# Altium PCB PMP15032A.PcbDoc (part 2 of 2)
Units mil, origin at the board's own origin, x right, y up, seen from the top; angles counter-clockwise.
Board outline 3900 x 2580 mil, 6 copper layers (Top Layer, Signal Layer 1, Signal Layer 2, Signal Layer 3, Signal Layer 4, Bottom Layer), stack 61.668 mil thick; 127 components, 51 nets, 282 pads, 427 vias.
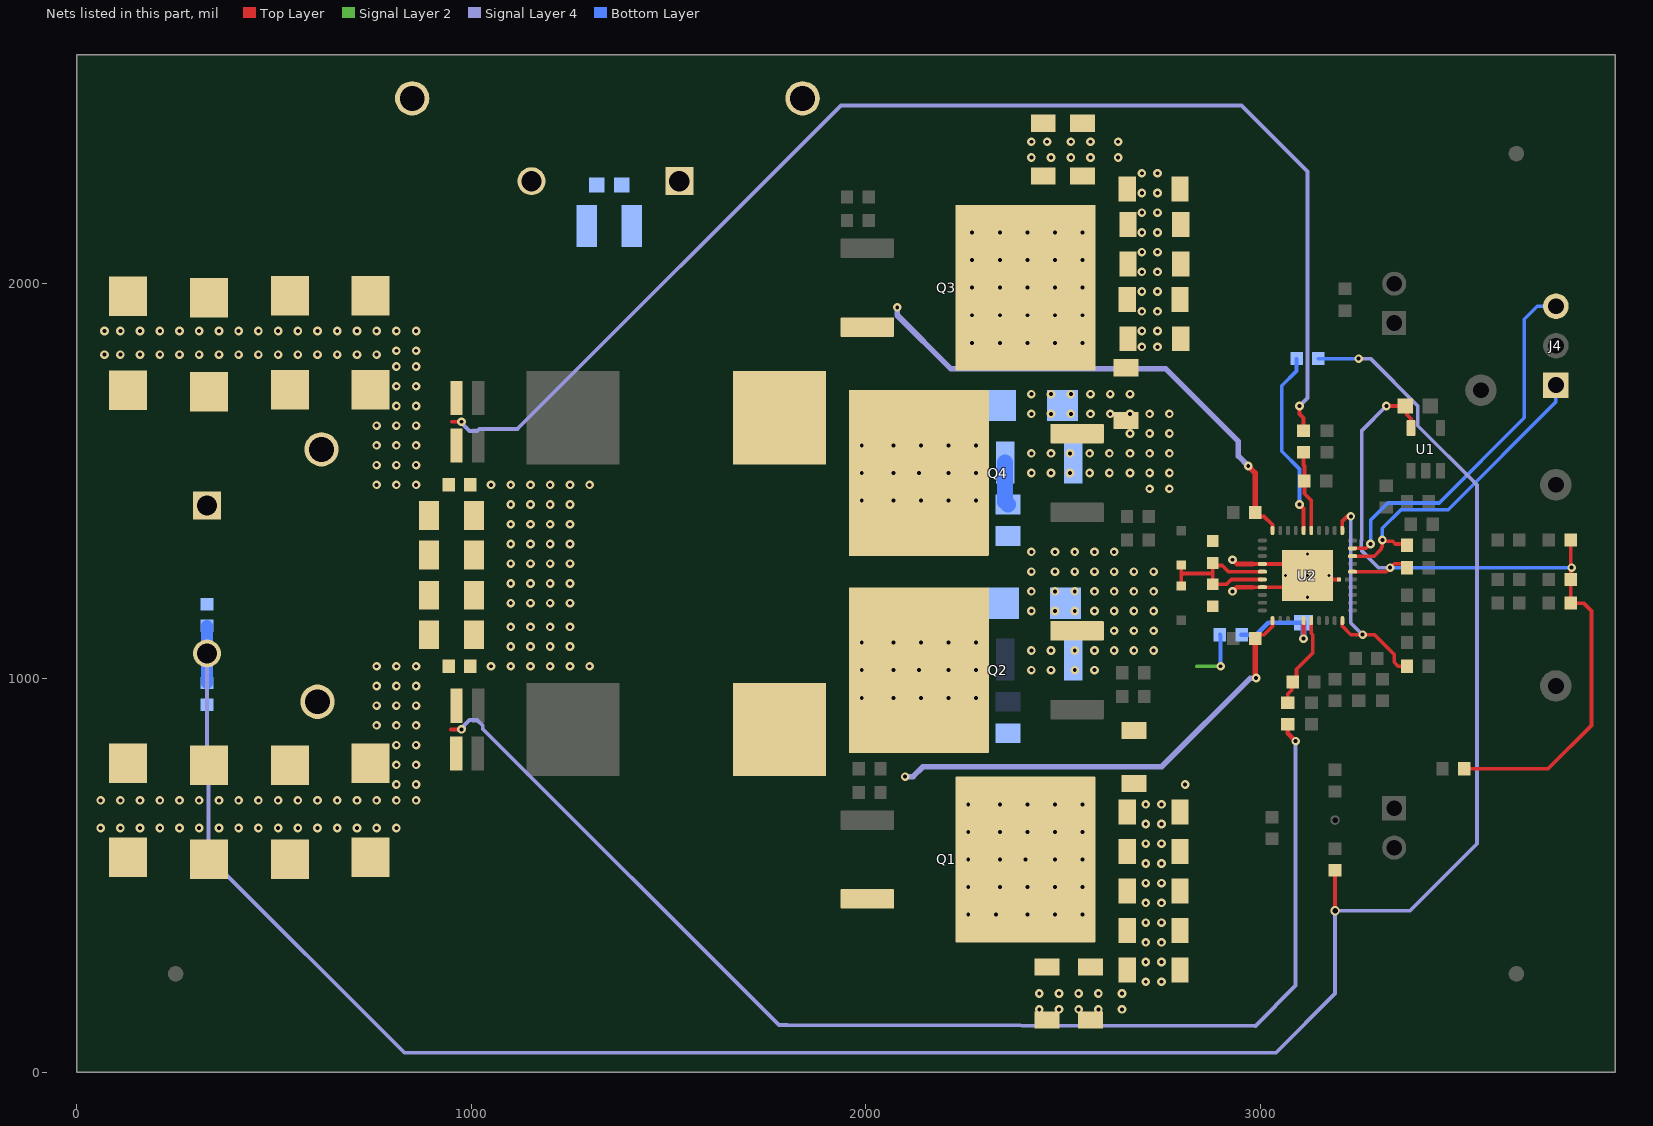
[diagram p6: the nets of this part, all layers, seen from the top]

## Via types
v1: diameter 22, hole 10, Top Layer to Bottom Layer, tented both sides, 319 vias
v2: diameter 22, hole 10, Top Layer to Bottom Layer, 102 vias
v3: diameter 19.68, hole 7.87, Top Layer to Bottom Layer, 5 vias
v4: diameter 22, hole 10, Top Layer to Bottom Layer, tented bottom, 1 vias

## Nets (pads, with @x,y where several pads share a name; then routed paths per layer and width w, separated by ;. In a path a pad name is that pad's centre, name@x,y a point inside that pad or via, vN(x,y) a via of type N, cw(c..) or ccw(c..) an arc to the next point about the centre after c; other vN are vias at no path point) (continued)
SGND: C1.1 C2.2 C3.2 C4.2 C5.2 C6.2 C7.1 C10.1 C11.1 C12.1 C13.1 C14.1 C15.1 C16.1 C17.1 C23.2 C25.1 C27.1 C29.2 C31.2 C35.1 C36.2 C37.2 C38.2 C39.2 C40.2 C41.2 C42.2 C43.2 C44.2 C45.2 C46.2 C47.2 C48.2 C49.1 C50.2 C51.2 D1.2 D4.2 J1.1 J2.1 NT1.2 Q2.3 Q4.3 R9.1 R28.1 TP2.1 TP4.1 U2.14 U2.17 U2.41 | length 413.8
  Top Layer w9.5: 2980.47,1230.47 U2.17@3005.83,1230.47 U2.41@3090.47,1230.47 ; 2980.47,1289.53 U2.14@3005.83,1289.53 U2.41@3090.47,1289.53 ; v3(3120,1260) 3130,1250 NT1.2@3200,1250
  Top Layer w12: v4(2930,1220) 2940.47,1230.47 2980.47,1230.47 ; v2(2930,1300) 2940.47,1289.53 2980.47,1289.53
  other v1: 2440,160 2490,160 2540,160 2590,160 2650,160 2750,230 2750,280 2750,330 2750,380 2750,430 2750,480 2750,530 2750,580 60,620 110,620 160,620 210,620 260,620 310,620 360,620 410,620 460,620 510,620 560,620 610,620 660,620 710,620 760,620 810,620 2750,630 2750,680 2810,730 2420,1020 2470,1020 2530,1020 2580,1020 1050,1030 1100,1030 1150,1030 1200,1030 1250,1030 1300,1030 2420,1070 2470,1070 2530,1070 2580,1070 2630,1070 2680,1070 2730,1070 1100,1080 1150,1080 1200,1080 1250,1080 2630,1120 2680,1120 2730,1120 1100,1130 1150,1130 1200,1130 1250,1130 2420,1170 2480,1170 2530,1170 2580,1170 2630,1170 2680,1170 2730,1170 1100,1190 1150,1190 1200,1190 1250,1190 2420,1220 2480,1220 2530,1220 2580,1220 2630,1220 2680,1220 2730,1220 1100,1240 1150,1240 1200,1240 1250,1240 2420,1270 2480,1270 2530,1270 2580,1270 2630,1270 2680,1270 2730,1270 1100,1290 1150,1290 1200,1290 1250,1290 2420,1320 2480,1320 2530,1320 2580,1320 2630,1320 1100,1340 1150,1340 1200,1340 1250,1340 1100,1390 1150,1390 1200,1390 1250,1390 1100,1440 1150,1440 1200,1440 1250,1440 2720,1480 2770,1480 1050,1490 1100,1490 1150,1490 1200,1490 1250,1490 1300,1490 2420,1520 2470,1520 2517.8,1520 2567.8,1520 2617.8,1520 2670,1520 2720,1520 2770,1520 2420,1570 2470,1570 2517.8,1570 2567.8,1570 2617.8,1570 2670,1570 2720,1570 2770,1570 2670,1620 2720,1620 2770,1620 2420,1670 2470,1670 2520,1670 2570,1670 2620,1670 2670,1670 2720,1670 2770,1670 2420,1720 2470,1720 2520,1720 2570,1720 2620,1720 2670,1720 2740,1840 70,1880 110,1880 160,1880 210,1880 260,1880 310,1880 360,1880 410,1880 460,1880 510,1880 560,1880 610,1880 660,1880 710,1880 760,1880 810,1880 860,1880 2740,1880 2740,1930 2740,1980 2740,2030 2740,2080 2740,2130 2740,2180 2740,2230 2740,2280 2420,2360 2460,2360 2520,2360 2570,2360 2640,2360
  other v3: 3120,1204.88 3064.88,1260 3175.12,1260 3120,1315.12
SNUB2: C33.1 R28.2 | length 109.7
  Bottom Layer w40: R28.2@2353.39,1546.77 2353.39,1447.25 C33.1@2360.58,1440.06
SS: C21.1 U2.1 U2.30 | length 595
  Top Layer w9.5: U2.30@3208.58,1145.83 3208.58,1131.42 3230,1110 v1(3260,1110) 3290,1110 3340,1060 3340,1040 3350,1030 C21.1@3372.44,1030 ; U2.1@3208.58,1374.17 3208.58,1398.58 3220,1410 v2(3230,1410)
  Signal Layer 4 w9.5: v2(3230,1410) 3230,1140 v1(3260,1110)
SW1: C18.1 C22.1 D1.1 L1.1 Q1.3 Q2.4 U2.21 | length 1162.4
  Top Layer w9.5: C22.1@2987.56,1100 2997.56,1110 3010,1110 3031.42,1131.42 U2.21@3031.42,1145.83
  Top Layer w14: v1@2987.56,1002.44 C22.1@2987.56,1100
  Signal Layer 4 w14: v1(2100,750) 2120,750 2145.13,775.13 2750.3,775.13 2975.18,1000 v1(2990,1000)
  other v2: 1990,950 2070,950 2140,950 2210,950 2280,950 1990,1020 2070,1020 2135.51,1020 2210,1020 2280,1020 1990,1090 2070,1090 2140,1090 2210,1090 2280,1090
SW2: C30.1 C33.2 D4.1 L2.2 Q3.3 Q4.4 U2.10 | length 1276.6
  Top Layer w9.5: C30.1@2987.56,1420 2997.56,1410 3010,1410 3031.42,1388.58 U2.10@3031.42,1374.17
  Top Layer w14: v1(2970,1537.59) 2987.56,1520.03 C30.1@2987.56,1420
  Signal Layer 4 w14: v1@2080,1930 2080,1920 2215.13,1784.87 2760.3,1784.87 2944.87,1600.3 2944.87,1562.71 v1(2970,1537.59)
  other v1: 2080,1940
  other v2: 1990,1450 2070,1450 2140,1450 2210,1450 2280,1450 1990,1520 2070,1520 2135.51,1520 2210,1520 2280,1520 1990,1590 2070,1590 2140,1590 2210,1590 2280,1590
SYNC_IN: J4.1 R32.2 U2.38 | length 823.6
  Top Layer w9: U2.38@3234.17,1309.21 3289.21,1309.21 3306.63,1326.63 3306.63,1329.68 3310,1333.06 v2(3310,1350) 3313.37,1346.63 3336.43,1346.63 3343.06,1340 R32.2@3372.44,1340
  Bottom Layer w9: v2(3310,1350) 3310,1380 3357.12,1427.12 3477.12,1427.12 3750,1700 J4.1@3750,1750
SYNC_OUT: J4.3 U2.39 | length 951.7
  Top Layer w9: U2.39@3234.17,1328.9 3268.9,1328.9 v2(3280,1340)
  Bottom Layer w9: v2(3280,1340) 3280,1400 3324,1444 3454,1444 3670,1660 3670,1910 3702.85,1942.85 J4.3@3750,1942.85
VCC: C23.1 C25.2 D2.2 D3.2 U2.15 U2.16 | length 455.3
  Top Layer w9.5: D2.2@2800,1233.31 2800,1260 ; D3.2@2800,1286.69 2800,1260 ; U2.16@3005.83,1250.16 2926.75,1250.16 2914.59,1238 C25.2@2880,1238 2880,1265 ; U2.15@3005.83,1269.84 2919.66,1269.84 2903.93,1285.57 2886.43,1285.57 C23.1@2880,1292 2880,1265 ; 2800,1260 2805,1265 2880,1265
VCCX: R22.2 U2.6 | length 474.2
  Top Layer w9.5: v2(3100,1440) 3110.16,1429.84 U2.6@3110.16,1374.17
  Bottom Layer w9.5: R22.2@3092.44,1810 3092.44,1778.65 3055.04,1741.25 3055.04,1574.96 3100,1530 v2(3100,1440)
VDDA: C8.1 C28.1 R5.2 R17.2 R20.1 R26.2 U1.5 U2.36 | length 2069.9
  Top Layer w9.5: U2.36@3234.17,1269.84 3319.84,1269.84 v2(3329.92,1279.92) 3340,1290 C28.1@3372.44,1290 ; v1(3320,1690) C8.1@3368.5,1690 3372.44,1690 3372.44,1667.56 3382.6,1657.4 U1.5@3382.6,1634.13 ; R5.2@3517.56,770 3730,770 3840,880 3840,1170 3820,1190 R20.1@3787.56,1190 v1@3787.56,1270 ; v1@3787.56,1282.44 R17.2@3787.56,1350
  Signal Layer 4 w9.5: v1(3320,1690) 3258.01,1628.01 3258.01,1351.42 3256.38,1349.79 3256.38,1330.21 3258.01,1328.58 3258.01,1321.99 3300.08,1279.92 v2(3329.92,1279.92)
  Bottom Layer w9.5: v2(3329.92,1279.92) 3789.92,1279.92 v1(3790,1280)
VIN: C10.2 C11.2 C12.2 C13.2 C14.2 C15.2 C16.2 C17.2 C29.1 C31.1 C37.1 C38.1 C39.1 C40.1 C41.1 C42.1 C43.1 C44.1 J2.2 Q1.4 Q3.4 R19.2 TP3.1 | length 140.8
  Signal Layer 2 w10: 2840,1030 v1(2900,1030)
  Bottom Layer w10: R19.2@2897.99,1110 2900,1107.99 v1(2900,1030)
  other v1: 2440,200 2490,200 2540,200 2590,200 2650,200 2710,230 2710,280 2710,330 2710,380 2710,430 2710,480 2710,530 2710,580 2710,630 2710,680 2700,1840 2700,1880 2700,1930 2700,1980 2700,2030 2700,2080 2700,2130 2700,2180 2700,2230 2700,2280 2420,2320 2470,2320 2520,2320 2570,2320 2640,2320
  other v2: 2260,400 2330,400 2410,400 2480,400 2550,400 2260,470 2340,470 2410,470 2480,470 2550,470 2260,540 2340,540 2405.51,540 2480,540 2550,540 2260,610 2340,610 2410,610 2480,610 2550,610 2260,680 2340,680 2410,680 2480,680 2550,680 2270,1850 2340,1850 2410,1850 2480,1850 2550,1850 2270,1920 2340,1920 2410,1920 2480,1920 2550,1920 2270,1990 2340,1990 2410,1990 2480,1990 2550,1990 2270,2060 2340,2060 2410,2060 2480,2060 2550,2060 2270,2130 2340,2130 2410,2130 2480,2130 2550,2130
VIN_IC: C27.2 R19.1 U2.25 | length 255.5
  Top Layer w9.5: v2@3110.16,1100.16 U2.25@3110.16,1145.83
  Top Layer w12: v2(3110,1100) v2@3110.16,1100.16
  Bottom Layer w12: R19.1@2953.11,1110 2990,1110 3020.63,1140.63 C27.2@3110,1140.63
  Bottom Layer w16: v2(3110,1100) C27.2@3110.16,1140
VO1_IC: C9.2 R6.1 U2.26 | length 228.6
  Top Layer w9.5: R6.1@3070,937.56 3070,960 3080,970 C9.2@3080,987.56 ; C9.2@3092.44,990 3092.44,1022.44 3133.62,1063.62 3133.62,1109.79 3129.84,1113.57 U2.26@3129.84,1145.83
VO2_IC: C34.1 R31.1 U2.5 | length 206.5
  Top Layer w9.5: R31.1@3110,1572.44 3110,1540 3112.44,1537.56 C34.1@3112.44,1500 3112.44,1467.56 3129.84,1450.16 U2.5@3129.84,1374.17
VOUT: C1.2 C2.1 C3.1 C4.1 C5.1 C6.1 C7.2 C35.2 C36.1 C45.1 C46.1 C47.1 C48.1 C49.2 C50.1 C51.1 J1.2 R2.2 R6.2 R7.1 R7A.1 R22.1 R30.2 R30A.2 R31.2 TP1.1 TP7.1 | length 12457.1
  Top Layer w10: 948.59,870 v1@970,870 ; 950.28,1650 v1@970,1650 ; v1(3100,1690) 3100,1670 3110,1660 R31.2@3110,1627.56 ; TP7.1@3190,410 R2.2@3190,512.44
  Top Layer w12: R6.2@3070,882.44 3070,860 v1(3090,840)
  Signal Layer 4 w9.5: TP7.1@3190,410 3380,410 3550,580 3550,1490 3400,1640 3400,1690 3280,1810 v1(3250,1810)
  Signal Layer 4 w10: J1.2@330,1062.6 330,750 333.87,746.13 333.87,546.13 830,50 3040,50 3190,200 TP7.1@3190,410 ; v1(610,1820) v1@610.39,1820 ; v1@970,870 980,870 981.13,871.13 981.13,879.89 995.11,893.87 1014.89,893.87 1028.87,879.89 1028.87,871.4 1780.28,120 1800,120 2987.87,117.87 3090,220 v1(3090,840) ; v1(975,1650) 975,1646.24 995.11,1626.13 1014.89,1626.13 1020.89,1632.13 1117.4,1632.13 1937.4,2452.13 2952.6,2452.13 3120,2284.72 3120,1710 v1(3100,1690)
  Bottom Layer w9.5: R22.1@3147.56,1810 v1(3250,1810)
  Bottom Layer w30: C49.2@330,987.56 J1.2@330,1062.6 C1.2@330,1132.44
  other v1: 60,690 110,690 160,690 210,690 260,690 310,690 360,690 410,690 460,690 510,690 560,690 610,690 660,690 710,690 760,690 810,690 860,690 810,730 860,730 810,780 860,780 810,830 860,830 975,870 760,880 810,880 860,880 760,930 810,930 860,930 760,980 810,980 860,980 760,1030 810,1030 860,1030 760,1490 810,1490 860,1490 760,1540 810,1540 860,1540 760,1590 810,1590 860,1590 760,1640 810,1640 860,1640 810,1690 860,1690 810,1740 860,1740 810,1790 860,1790 70,1820 110,1820 160,1820 210,1820 260,1820 310,1820 360,1820 410,1820 460,1820 510,1820 560,1820 660,1820 710,1820 760,1820 810,1830 860,1830
pads on no net: FID1.1 FID2.1 FID3.1 FID4.1 FID5.1 FID6.1 H1.0 H2.0 H3.0 H4.0 U2.0

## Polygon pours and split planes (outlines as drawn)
NetL2_1 on Top Layer "TOP_LAYER_NETL2_1_P299" (solid, pour order 299): 1050,1980 1360,1980 1380,1960 1380,1540 1370,1530 1036.46,1530 1010,1556.46 1010,1940
NetL1_2 on Top Layer "TOP_LAYER_NETL1_2_P300" (solid, pour order 300): 1035,1000 1370,1000 1380,990 1380,560 1360,540 1050,540 1010,580 1010,975
AGND on Top Layer "TOP_LAYER_AGND_P301" (solid, pour order 301): 3170,970 3170,870 3520,870 3620,970 3620,1800 3400,1800 3400,1010 3360,970
SGND on Top Layer "TOP_LAYER_SGND_P298" (solid, pour order 298): 2950,1210 2950,1350 2910,1390 2820,1390 2820,1140 2880,1140
SW2 on Top Layer "TOP_LAYER_SW2_P304" (solid, pour order 304): 2370,1300 1580,1300 1540,1340 1540,1940 1580,1980 2103.23,1980 2130,1953.23 2130,1770 2150,1750 2291.5,1750 2360,1750 2390,1720 2390,1320
VIN on Top Layer "TOP_LAYER_VIN_P302" (solid, pour order 302): 2170,1760 2696.18,1760 2720,1783.82 2720,2310 2690,2340 2190,2340 2148.62,2298.62 2148.62,1781.38
VIN on Top Layer "TOP_LAYER_VIN_P303" (solid, pour order 303): 2177.52,760 2717.34,760 2730,747.34 2730,200 2710,180 2169.96,180 2147.58,202.48 2149.88,732.48
SW1 on Top Layer "TOP_LAYER_SW1_P305" (solid, pour order 305): 2343.66,1238.11 1588.11,1238.11 1540,1190 1540,420 1580,380 2100,380 2130,410 2130,760 2161.81,791.81 2341.81,791.81 2370,820 2370,910 2370,1211.77
SGND on Top Layer "TOP_LAYER_SGND_P307" (solid, pour order 307): 0,0 0,2580 3900,2580 3900,0
VOUT on Top Layer "Top Layer-No Net" (solid, pour order 306): 970,658.03 970,1848.03 5.43,1848.03 5.43,658.03
SGND on Bottom Layer "BOTTOM_LAYER_SGND_P318" (solid, pour order 318): 0,0 0,2580 3900,2580 3900,0
SW2 on Bottom Layer "Bottom Layer-No Net" (solid, pour order 317): 1964.45,1310 2382.56,1310 2391.38,1318.82 2391.38,1721.77 2383.15,1730 1965,1730 1950,1715 1950,1324.45
SW1 on Bottom Layer "Bottom Layer-No Net" (solid, pour order 316): 1964.45,810 2382.95,810 2391.38,818.43 2391.38,1230 1965,1230 1950,1215 1950,824.45
VIN on Bottom Layer "BOTTOM_LAYER_VIN_P315" (solid, pour order 315): 2167.05,2190 2580,2190 2592.62,2177.38 2592.62,1802.62 2578.62,1788.62 2161.38,1788.62 2150,1800 2150,2172.95
VIN on Bottom Layer "BOTTOM_LAYER_VIN_P314" (solid, pour order 314): 2162.56,742.56 2577.44,742.56 2592.62,727.38 2592.62,352.62 2578.62,338.62 2161.38,338.62 2148.75,351.25 2148.75,728.75
SGND on Signal Layer 1 "SIGNAL_LAYER_1_SGND_P308" (solid, pour order 308): 0,0 0,2580 3900,2580 3900,0
SGND on Signal Layer 2 "Signal Layer 2-No Net" (solid, pour order 310): 2870,2580 3900,2580 3900,0 2870,0
VIN on Signal Layer 2 "SIGNAL_LAYER_2_VIN_P311" (solid, pour order 311): 0,0 0,2580 2860,2580 2860,0
VOUT on Signal Layer 2 "Top Layer-No Net" (solid, pour order 309): 930,658.59 930,1848.59 2.82,1848.59 2.82,658.59
SGND on Signal Layer 3 "SIGNAL_LAYER_3_SGND_P312" (solid, pour order 312): 0,0 0,2580 3900,2580 3900,0
SGND on Signal Layer 4 "SIGNAL_LAYER_4_SGND_P313" (solid, pour order 313): 0,0 0,2580 3900,2580 3900,0

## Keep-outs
Keep-Out Layer:
  the board outline again, w7
  text ".Layer_Name" at 577,-1148.49 h60

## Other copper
Top Layer:
  pour cut-out: 962.67,1666.71 1016.26,1666.71 1024.78,1658.19 1024.78,1639.29 1016.94,1631.81 963.01,1631.81 955.22,1639.6 955.22,1659.26
  pour cut-out: 962.67,886.71 1016.26,886.71 1024.78,878.19 1024.78,859.29 1016.94,851.81 962.85,851.81 955.22,859.6 955.22,879.26
  text ".Layer_Name" at 577,-1148.49 h60
Signal Layer 1:
  text "'.Layer_Name'" at 577,-1148.49 h60
Signal Layer 2:
  text "'.Layer_Name'" at 577,-1148.49 h60
Signal Layer 3:
  text "'.Layer_Name'" at 577,-1148.49 h60
Signal Layer 4:
  text "'.Layer_Name'" at 577,-1148.49 h60
Bottom Layer:
  rectangle net VIN: 1110,2090 1340,2290
  text ".Layer_Name" at 577,-1148.49 h60

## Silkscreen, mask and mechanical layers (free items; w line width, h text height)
Top Overlay:
  text "-" at 1790,2310 h100
  text "+" at 810,2300 h100
  text "VIN" at 780,2110 h60
  text "SYNCOUT" at 3600,2010 h40
  text "AGND" at 3460,1800 h40
  text "SYNCIN" at 3640,1630 h40
  text "-" at 580,1430 h100
  text "VOUT" at 640,1170 h60 r90
  text "+" at 570,1020 h100
  text "'.PRJ_Number'.PCB_Rev" at 870,90 h108.27
  text "LM5140 DUAL / INTERLEAVED / HI CURRENT" at 3000,40 h50
  text ".Layer_Name" at 577,-1148.49 h60
Bottom Overlay:
  text ".Layer_Name" at 577,-1148.49 h60
Top Paste:
  text ".Layer_Name" at 577,-1148.49 h60
Bottom Paste:
  text ".Layer_Name" at 577,-1148.49 h60
Top Solder:
  text ".Layer_Name" at 577,-1148.49 h60
  text ".Layer_Name" at 577,-1148.49 h60
Bottom Solder:
  text ".Layer_Name" at 577,-1148.49 h60
Drill Guide:
  text ".Layer_Name" at 577,-1148.49 h60
M1 Board Outline:
  the board outline again, w10
  text ".Layer_Name" at 577,-1148.49 h60
M2 Board Dimensions:
  rectangle: 125,-690 500,-565
  rectangle: 0,-565 125,-440
  lines w7: 0,-565 1000,-565 ; 125,-690 125,-440 ; 250,-690 250,-440 ; 500,-690 500,-440 ; 750,-690 750,-440 ; 0,-690 0,-440 1000,-440 1000,-690 0,-690
  text ".Layer_Name" at 577,-1148.49 h60
M3 3D STEP Top:
  text ".Layer_Name" at 577,-1148.49 h60
M4 3D STEP Bottom:
  text ".Layer_Name" at 577,-1148.49 h60
M5 Assembly Top:
  lines w10: -292,-1220.17 6308,-1220.17 ; -292,-1016.83 6310,-1016.83 ; -292,-813.5 -292,-1423.5 3713,-1423.5 6310,-1423.5 6310,-813.5 -291.5,-813.5 -291.5,-1423.5 1284,-1423.5 ; 2173,-1423.5 2173,-813.5 ; 3440,-1016.83 3440,-813.5 ; 4280,-1016.83 4280,-813.5 ; 4902,-1430 4902,-1227.17
  text "COMPONENTS MARKED 'DNP' SHOULD NOT BE POPULATED." at 1153.5,-608.5 h60
  text "ASSEMBLY VARIANT:" at 1153,-724 h60
  text ".VariantName" at 2189,-724 h60
  text "PCB VIEWED FROM TOP SIDE" at -228.5,-945.67 h60
  text "BOARD #:" at 2248,-945.67 h60
  text ".PRJ_Number" at 2793.5,-945.67 h60
  text "REV:" at 3638,-945.67 h60
  text ".PCB_Rev" at 3929.5,-945.67 h60
  text "SVN REV:" at 4476,-945.67 h60
  text ".VersionControl_RevNumber" at 4982,-945.67 h60
  text "TID #:" at 2248,-1149 h60
  text ".TID" at 2793.5,-1149 h60
  text "PLOT NAME =" at -228.5,-1354.34 h60
  text ".plot_File_Name" at 577,-1354.34 h60
  text "GENERATED    :" at 2250,-1354.34 h60
  text ".Print_Date" at 3119.5,-1354.34 h60
  text ".Print_Time" at 3848.5,-1354.34 h60
  text "TEXAS INSTRUMENTS" at 5113,-1354.34 h60
M6 Assembly Bottom:
  lines w10: -292.5,-1017.33 6309.5,-1017.33 ; -290.5,-1220.67 6309.5,-1220.67 ; 1115.5,-1430.5 1115.5,-1227.67 ; 1737.5,-1017.33 1737.5,-814 ; 2577.5,-1017.33 2577.5,-814 ; 3844.5,-1424 3844.5,-814 ; 4733.5,-1424 6309,-1424 6309,-814 -292.5,-814 -292.5,-1424 2304.5,-1424 6309.5,-1424 6309.5,-814
  text "COMPONENTS MARKED 'DNP' SHOULD NOT BE POPULATED." at 6102,-608 h60
  text ".VariantName" at 5058,-724 h60
  text "ASSEMBLY VARIANT:" at 6097,-724 h60
  text ".VersionControl_RevNumber" at 1035.5,-946.17 h60
  text "SVN REV:" at 1541.5,-946.17 h60
  text ".PCB_Rev" at 2088,-946.17 h60
  text "REV:" at 2379.5,-946.17 h60
  text ".PRJ_Number" at 3224,-946.17 h60
  text "BOARD #:" at 3769.5,-946.17 h60
  text "PCB VIEWED FROM BOTTOM SIDE" at 6246,-946.17 h60
  text ".TID" at 3224,-1149.5 h60
  text "TID #:" at 3769.5,-1149.5 h60
  text "TEXAS INSTRUMENTS" at 904.5,-1354.84 h60
  text ".Print_Time" at 2169,-1354.84 h60
  text ".Print_Date" at 2898,-1354.84 h60
  text "GENERATED    :" at 3767.5,-1354.84 h60
  text ".plot_File_Name" at 5440.5,-1354.84 h60
  text "PLOT NAME =" at 6246,-1354.84 h60
M9 Title Sheet:
  drawing of 57 lines, arcs and shapes, not listed
  text "1" at 739.84,7746.5 h70
  text "2" at 3235.5,7746.5 h70
  text "3" at 5724.84,7746.5 h70
  text "4" at 8231.51,7746.5 h70
  text "5" at 10730.5,7746.5 h70
  text "6" at 13235.5,7746.5 h70
  text "A" at -416.5,6603.5 h70
  text "A" at 14383.5,6603.5 h70
  text "B" at -416.5,4223.5 h70
  text "B" at 14383.5,4223.5 h70
  text "C" at -416.5,1848.5 h70
  text "C" at 14383.5,1848.5 h70
  text "PROJECT TITLE:" at 11343.5,-12.5 h45
  text ".PRJ_Title" at 11393.5,-145.83 h70
  text "DESIGNED FOR:" at 11343.5,-313.5 h45
  text ".PRJ_Customer" at 11393.5,-453.5 h70
  text "D" at -416.5,-521.5 h70
  text "D" at 14383.5,-521.5 h70
  text "FILE NAME:" at 11343.5,-613.5 h45
  text ".PCB_File_Name_No_Path" at 11393.5,-733.5 h70
  text "Texas Instruments (TI) and/or its licensors do not warrant the accuracy or completeness of this specification" at 6374,-895.34 h45
  text "ENGINEER:" at 11343.5,-903.5 h45
  text "LAYOUT BY:" at 12848.5,-903.5 h45
  text "or any information contained therein. TI and/or its licensors do not warrant that this design will meet" at 6329.01,-1008 h45
  text ".PRJ_Engineer" at 11393.5,-1058.49 h70
  text ".PCB_Layout" at 12899,-1058.49 h70
  text "the specifications, will be suitable for your application or fit for any particular purpose, or will operate in" at 6329.01,-1120.67 h45
  text ".Layer_Name" at 577,-1148.49 h60
  text "ALTIUM DESIGNER VERSION:" at 12848.5,-1213.5 h45
  text "an implementation. TI and/or its licensors do not warrant that the design is production worthy. You should" at 6329.01,-1233.33 h45
  text "completely validate and test your design implementation to confirm the system functionality for your application." at 6374,-1346 h45
  text ".print_Scale" at 11393.5,-1346.83 h70
  text ".Application_BuildNumber" at 12899,-1346.83 h70
  text "1" at 739.84,-1553.5 h70
  text "2" at 3235.5,-1553.5 h70
  text "3" at 5724.84,-1553.5 h70
  text "4" at 8231.51,-1553.5 h70
  text "5" at 10730.5,-1553.5 h70
  text "6" at 13235.5,-1553.5 h70
M10 Fab Notes:
  drawing of 173 lines, arcs and shapes, not listed
  text "DESIGN INFORMATION" at 12378.02,5911 h60
  text "MIN. TRACK WIDTH:" at 11733.46,5731 h60
  text "8" at 12829.7,5731 h60
  text "MIL" at 12984.46,5731 h60
  text "MIN. CLEARANCE:" at 11733.46,5599 h60
  text "0.2" at 12769.7,5599 h60
  text "mm" at 12984.46,5599 h60
  text "MIN. VIA PAD SIZE:" at 11733.46,5467 h60
  text "24" at 12799.71,5467 h60
  text "MIL" at 12984.46,5467 h60
  text "0.05mm (2MIL)" at 12428.46,5325.29 h60
  text "MINIMUM ANNULAR RING" at 11404.23,5321 h60
  text "EXTERNAL" at 13136.46,5321 h60
  text "PER" at 11604.23,5203 h60
  text "IPC-D-275 CLASS 2 LEVEL C" at 11824.23,5203 h60
  text "MIL, HOLES" at 13312.46,5090.71 h60
  text "+/-" at 12920,5090 h60
  text "+/-" at 13774,5090 h60
  text "REGISTRATION TOLERANCES:" at 11404.23,5085 h60
  text "METAL" at 12604,5085 h60
  text "5" at 13180.2,5085 h60
  text "3" at 14013.2,5085 h60
  text "MIL" at 14129.46,5085 h60
  text "+/-" at 13774,4972 h60
  text "HOLE SIZE TOLERANCE (UNLESS OTHERWISE SPECIFIED):" at 11404.23,4967 h60
  text "3" at 14013.2,4967 h60
  text "MIL" at 14129.46,4967 h60
  text "MATERIAL:" at 11329.46,4757.54 h60
  text "FR-4 High Tg" at 12315.9,4617.21 h60
  text "FR-408" at 11750.46,4608.64 h60
  text "OTHER" at 13238.46,4608.64 h60
  text "X" at 12161,4605 h60
  text "62 MIL (1.6mm) +/-10%" at 12070.56,4445.92 h60
  text "THICKNESS:" at 11404.23,4441.64 h60
  text "X" at 11942.4,4441.64 h60
  text "OTHER" at 13355.46,4441.64 h60
  text "TOLERANCE:" at 11404.23,4283.64 h60
  text "X" at 12243.53,4283.64 h60
  text "ANSI IPC-6012 TYPE 3 CLASS 2" at 12430.48,4283.64 h60
  text "OTHER +/-" at 12430.46,4127.64 h60
  text "BOW & TWIST:" at 11404.23,3970.64 h60
  text "X" at 12243.53,3970.64 h60
  text "ANSI IPC-6012 TYPE 3 CLASS 2" at 12430.48,3970.64 h60
  text "OTHER +/-" at 12430.46,3812.13 h60
  text "DRILLING:" at 11329.46,3673.64 h60
  text "REFERENCE:" at 11404.23,3556.64 h60
  text "X" at 12052.46,3556.64 h60
  text "AS SHOWN" at 12239.46,3556.64 h60
  text "X" at 12953.46,3556.64 h60
  text "NC_DRILL FILES" at 13090.46,3556.64 h60
  text "PTH COPPER THICKNESS:" at 11404.23,3398.64 h60
  text "X" at 12534.46,3398.64 h60
  text "20-30 um" at 12671.46,3398.64 h60
  text "OTHER" at 13388.46,3398.64 h60
  text "BOARD FINISH:" at 11329.46,3239.64 h60
  text "SILKSCREEN:" at 11484.68,3121.64 h60
  text "X" at 12433.46,3121.64 h60
  text "TOP" at 12559.46,3121.64 h60
  text "X" at 12943.46,3121.64 h60
  text "BOTTOM" at 13070.46,3121.64 h60
  text "SILKSCREEN COLOR:" at 11484.68,2954.64 h60
  text "X" at 12432.42,2954.64 h60
  text "WHITE" at 12559.46,2954.64 h60
  text "OTHER" at 13070.46,2954.64 h60
  text "X" at 12563.42,2795.44 h60
  text "GREEN" at 12690.46,2795.44 h60
  text "OTHER" at 13308.46,2795.44 h60
  text "SOLDER RESIST COLOR:" at 11484.68,2784.64 h60
  text "X" at 12563.42,2625.44 h60
  text "MATTE" at 12690.46,2625.44 h60
  text "SEMI-GLOSS" at 13308,2624.8 h60
  text "IMMERSION GOLD (ENIG)" at 12390.46,2436.92 h60
  text "ENEPIG" at 13728,2433.64 h60
  text "SURFACE FINISH:" at 11329.46,2432.64 h60
  text "X" at 12203.51,2432.64 h60
  text "IMM. TIN/SILVER OR EQUIV" at 11659,2275.64 h60
  text "OTHER" at 13090.46,2275.64 h60
  text "X" at 12200,2100 h60
  text "ARRAY/PANEL:" at 11329.46,2096.64 h60
  text "CUT AND TRIM PER M1 BOARD OUTLINE" at 12390.46,2092.35 h60
  text "N.C. ROUTE" at 12390.46,1940.64 h60
  text "V. SCORE" at 13256.46,1940.64 h60
  text "CERTIFICATION:" at 11329.46,1803.64 h60
  text "MATERIALS AND WORKMANSHIP FOR ALL PCBS" at 12054.46,1803.64 h60
  text "TO MEET OR EXCEED THE REQUIREMENTS OF:" at 12054.46,1705.64 h60
  text "X" at 11680.96,1569.13 h60
  text "ANSI IPC-A-600F CLASS ->" at 11819.96,1569.13 h60
  text "X" at 13459.02,1569.13 h60
  text "2" at 13577.96,1569.14 h60
  text "1" at 13262.96,1567.64 h60
  text "3" at 13931.96,1567.64 h60
  text "X" at 12495.02,1409.64 h60
  text "RoHS" at 12631.96,1409.64 h60
  text "OTHER" at 13276.36,1409.64 h60
  text "PER ORDER" at 13673.42,1409.64 h60
  text "ALL BOARDS MUST MEET OR EXCEED UL94-V0 REQUIREMENTS." at 11357,1244 h60
  text "PCB MUST BEAR THE UL94V-0 UL REGISTERED MATERIAL ID NUMBER" at 11357,1124 h60
  text "ADDITIONAL REQUIREMENTS:" at 11329.46,950.64 h60
  text "MICROSECTION:" at 11404.23,835.64 h60
  text "YES" at 12309.96,835.64 h60
  text "REQUIRED" at 13171.46,679.49 h60
  text "BARE BOARD ELEC. TEST:" at 11404.23,676.64 h60
  text "NONE" at 12709.96,676.64 h60
  text "X" at 13044.46,676.64 h60
  text "PER ORDER" at 13763.46,676.64 h60
  text ".Layer_Name" at 577,-1148.49 h60
M11 Gerber Information:
  lines w10: -292,-1220.17 6308,-1220.17 ; -292,-1016.83 6310,-1016.83 ; -292,-813.5 -292,-1423.5 3713,-1423.5 6310,-1423.5 6310,-813.5 -291.5,-813.5 -291.5,-1423.5 1284,-1423.5 ; 2173,-1423.5 2173,-813.5 ; 3440,-1016.83 3440,-813.5 ; 4280,-1016.83 4280,-813.5 ; 4902,-1430 4902,-1227.17
  text "ALL ARTWORK VIEWED FROM TOP SIDE" at -228.5,-945.67 h60
  text "BOARD #:" at 2248,-945.67 h60
  text ".PRJ_Number" at 2793.5,-945.67 h60
  text "REV:" at 3638,-945.67 h60
  text ".PCB_Rev" at 3929.5,-945.67 h60
  text "SVN REV:" at 4476,-945.67 h60
  text ".VersionControl_RevNumber" at 4982,-945.67 h60
  text "LAYER NAME =" at -228.5,-1148.49 h60
  text "TID #:" at 2248,-1149 h60
  text ".TID" at 2793.5,-1149 h60
  text "PLOT NAME =" at -228.5,-1354.34 h60
  text ".plot_File_Name" at 577,-1354.34 h60
  text "GENERATED    :" at 2250,-1354.34 h60
  text ".Print_Date" at 3119.5,-1354.34 h60
  text ".Print_Time" at 3848.5,-1354.34 h60
  text "TEXAS INSTRUMENTS" at 5113,-1354.34 h60
M12 Stackup:
  drawing of 399 lines, arcs and shapes, not listed
  text "Layer" at 9790.58,7557.5 h60
  text "Name" at 10200.49,7557.5 h60
  text "Material" at 11140.23,7557.5 h60
  text "Thickness" at 12000,7557.5 h60
  text "Constant" at 12649.84,7557.5 h60
  text "Board Layer Stack" at 13219.7,7557.5 h60
  text "1" at 9790.58,7437.5 h60
  text "Top Overlay" at 10200.49,7437.5 h60
  text "2" at 9790.58,7317.5 h60
  text "Top Solder" at 10200.49,7317.5 h60
  text "Solder Resist" at 11140.23,7317.5 h60
  text "0.40mil" at 12000,7317.5 h60
  text "3.5" at 12649.84,7317.5 h60
  text "3" at 9790.58,7197.5 h60
  text "Top Layer" at 10200.49,7197.5 h60
  text "Copper" at 11140.23,7197.5 h60
  text "2.00mil" at 12000,7197.5 h60
  text "4" at 9790.58,7077.5 h60
  text "Dielectric1" at 10200.49,7077.5 h60
  text "FR-4" at 11140.23,7077.5 h60
  text "10.00mil" at 12000,7077.5 h60
  text "4.8" at 12649.84,7077.5 h60
  text "5" at 9790.58,6957.5 h60
  text "Signal Layer 1" at 10200.49,6957.5 h60
  text "Copper" at 11140.23,6957.5 h60
  text "1.42mil" at 12000,6957.5 h60
  text "6" at 9790.58,6837.5 h60
  text "Dielectric 2" at 10200.49,6837.5 h60
  text "10.00mil" at 12000,6837.5 h60
  text "4.2" at 12649.84,6837.5 h60
  text "7" at 9790.58,6717.5 h60
  text "Signal Layer 2" at 10200.49,6717.5 h60
  text "Copper" at 11140.23,6717.5 h60
  text "1.42mil" at 12000,6717.5 h60
  text "8" at 9790.58,6597.5 h60
  text "Dielectric 3" at 10200.49,6597.5 h60
  text "12.00mil" at 12000,6597.5 h60
  text "4.2" at 12649.84,6597.5 h60
  text "9" at 9790.58,6477.5 h60
  text "Signal Layer 3" at 10200.49,6477.5 h60
  text "Copper" at 11140.23,6477.5 h60
  text "1.42mil" at 12000,6477.5 h60
  text "10" at 9790.58,6357.5 h60
  text "Dielectric 4" at 10200.49,6357.5 h60
  text "10.00mil" at 12000,6357.5 h60
  text "4.2" at 12649.84,6357.5 h60
  text "11" at 9790.58,6237.5 h60
  text "Signal Layer 4" at 10200.49,6237.5 h60
  text "Copper" at 11140.23,6237.5 h60
  text "1.42mil" at 12000,6237.5 h60
  text "12" at 9790.58,6117.5 h60
  text "Dielectric 5" at 10200.49,6117.5 h60
  text "10.00mil" at 12000,6117.5 h60
  text "4.2" at 12649.84,6117.5 h60
  text "13" at 9790.58,5997.5 h60
  text "Bottom Layer" at 10200.49,5997.5 h60
  text "Copper" at 11140.23,5997.5 h60
  text "2.00mil" at 12000,5997.5 h60
  text "14" at 9790.58,5877.5 h60
  text "Bottom Solder" at 10200.49,5877.5 h60
  text "Solder Resist" at 11140.23,5877.5 h60
  text "0.40mil" at 12000,5877.5 h60
  text "3.5" at 12649.84,5877.5 h60
  text "15" at 9790.58,5757.5 h60
  text "Bottom Overlay" at 10200.49,5757.5 h60
  text ".Layer_Name" at 577,-1148.49 h60
M13 Component Bodies Top:
  text ".Layer_Name" at 577,-1148.49 h60
M14 Component Bodies Bottom:
  text ".Layer_Name" at 577,-1148.49 h60
M15 Courtyards Top:
  text ".Layer_Name" at 577,-1148.49 h60
M16 Courtyards Bottom:
  text ".Layer_Name" at 577,-1148.49 h60
Drill Drawing:
  lines w10: 5336.04,2328.02 5391.23,2328.02 5391.23,2383.21 5336.04,2383.21 5336.04,2328.02 ; 5336.04,2507.39 5391.23,2507.39 5363.63,2452.2 5336.04,2507.39 ; 5336.04,2590.17 5349.83,2590.17 5363.63,2576.37 5377.43,2590.17 5391.23,2590.17 5377.43,2603.97 5391.23,2617.76 5377.43,2617.76 5363.63,2631.56 5349.83,2617.76 5336.04,2617.76 5349.83,2603.97 5336.04,2590.17 ; 5336.04,2700.55 5363.63,2714.35 5391.23,2700.55 5377.43,2728.14 5391.23,2755.74 5363.63,2741.94 5336.04,2755.74 5349.83,2728.14 5336.04,2700.55 ; 5336.04,2824.72 5336.04,2838.52 5349.83,2852.32 5336.04,2866.12 5336.04,2879.91 5349.83,2879.91 5363.63,2866.12 5377.43,2879.91 5391.23,2879.91 5391.23,2866.12 5377.43,2852.32 5391.23,2838.52 5391.23,2824.72 5377.43,2824.72 5363.63,2838.52 5349.83,2824.72 5336.04,2824.72 ; 5336.04,2962.7 5349.83,2962.7 5349.83,2948.9 5377.43,2948.9 5377.43,2962.7 5391.23,2962.7 5391.23,2990.29 5377.43,2990.29 5377.43,3004.09 5349.83,3004.09 5349.83,2990.29 5336.04,2990.29 5336.04,2962.7
  lines w12: 5286,2290.77 8516.52,2290.77 ; 5286,3035.82 8516.52,3035.82 ; 5623.86,2166.59 5623.86,3160 ; 5955.86,2166.59 5955.86,3160 ; 6592.42,2166.59 6592.42,3160 ; 6851.53,2166.59 6851.53,3160 ; 7226.68,2166.59 7226.68,3160 ; 7950.06,2166.59 7950.06,3160 ; 5286,2166.59 8516.52,2166.59 8516.52,3160 5286,3160 5286,2166.59
  text "Symbol" at 5360.51,3073.08 h72
  text "Quantity" at 5661.11,3073.08 h72
  text "Finished Hole Size" at 5993.12,3073.08 h72
  text "Plated" at 6629.67,3073.08 h72
  text "Hole Type" at 6888.78,3073.08 h72
  text "Drill Layer Pair" at 7263.93,3073.08 h72
  text "Hole Tolerance" at 7987.32,3073.08 h72
  text "5" at 5661.11,2948.9 h60
  text "7.87mil (0.200mm)" at 5993.12,2948.9 h60
  text "PTH" at 6629.67,2948.9 h60
  text "Round" at 6888.78,2948.9 h60
  text "Top Layer - Bottom Layer" at 7263.93,2948.9 h60
  text "422" at 5661.11,2824.72 h60
  text "10.00mil (0.254mm)" at 5993.12,2824.72 h60
  text "PTH" at 6629.67,2824.72 h60
  text "Round" at 6888.78,2824.72 h60
  text "Top Layer - Bottom Layer" at 7263.93,2824.72 h60
  text "2" at 5661.11,2700.55 h60
  text "14.00mil (0.356mm)" at 5993.12,2700.55 h60
  text "PTH" at 6629.67,2700.55 h60
  text "Round" at 6888.78,2700.55 h60
  text "Top Layer - Bottom Layer" at 7263.93,2700.55 h60
  text "10" at 5661.11,2576.37 h60
  text "40.00mil (1.016mm)" at 5993.12,2576.37 h60
  text "PTH" at 6629.67,2576.37 h60
  text "Round" at 6888.78,2576.37 h60
  text "Top Layer - Bottom Layer" at 7263.93,2576.37 h60
  text "4" at 5661.11,2452.2 h60
  text "51.18mil (1.300mm)" at 5993.12,2452.2 h60
  text "PTH" at 6629.67,2452.2 h60
  text "Round" at 6888.78,2452.2 h60
  text "Top Layer - Bottom Layer" at 7263.93,2452.2 h60
  text "4" at 5661.11,2328.02 h60
  text "63.00mil (1.600mm)" at 5993.12,2328.02 h60
  text "PTH" at 6629.67,2328.02 h60
  text "Round" at 6888.78,2328.02 h60
  text "Top Layer - Bottom Layer" at 7263.93,2328.02 h60
  text "447 Total" at 5661.11,2203.84 h60
  text ".Layer_Name" at 577,-1148.49 h60
M17 Embedded Cavity:
  text ".Layer_Name" at 577,-1148.49 h60
M18 Embedded Assembly:
  text ".Layer_Name" at 577,-1148.49 h60
M19 Embedded Keepout:
  text ".Layer_Name" at 577,-1148.49 h60

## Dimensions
0,0 to 0,2580 on M2 Board Dimensions
0,0 to 3900,0 on M2 Board Dimensions
0,-690 to 1000,-690 on M2 Board Dimensions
